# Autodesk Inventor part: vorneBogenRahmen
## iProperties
Created: 2006-10
Part Number: vorneBogenRahmen
Document SubType Name: Sheet Metal
Designer: rr
Author: rr
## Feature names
1. Extrusion1
2. Grobblech1
